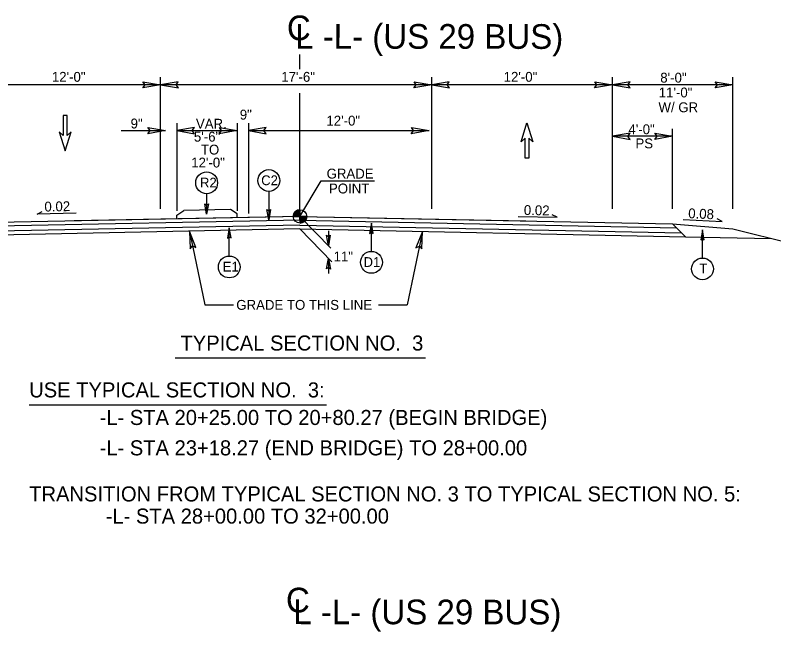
# Model space of a CAD drawing. Extents: x 1901582 to 1902252, y 193723 to 194156.
# Drawn here: x 1902027.7 to 1902078.1, y 194003.9 to 194044.9 of the extents above; entities that cross this region are included whole.
import ezdxf

# ---------------------------------------------------------------- set-up
doc = ezdxf.new("R2010")
doc.units = 0
for name, color, linetype in [('Old_Level_1', 7, 'Continuous'), ('Old_Level_11', 7, 'Continuous'), ('Old_Level_2', 7, 'Continuous'), ('Old_Level_20', 7, 'Continuous'), ('Prop Dimension', 7, 'Continuous'), ('Prop Dimension Text', 7, 'Continuous'), ('Typical Grade Point Symbol CELL', 7, 'Continuous'), ('Typical Pavement Slope Information CELL', 7, 'Continuous'), ('Typical Terminator CELL', 7, 'Continuous'), ('Typical Text Centerline CELL', 7, 'Continuous'), ('Typical Text Grade Point CELL', 7, 'Continuous')]:
    doc.layers.add(name, color=color, linetype=linetype)

# ---------------------------------------------------------------- blocks, each defined once
blk = doc.blocks.new('TERMINATOR')
at = {"layer": 'Typical Terminator CELL'}
blk.add_lwpolyline([(-0.469, 0.081), (0, 0), (-0.471, -0.083), (-0.411, 0)], close=True, dxfattribs=at)

msp = doc.modelspace()

# ---------------------------------------------------------------- linework, layer by layer
at = {"layer": 'Old_Level_1'}
for p, q in [((1902037.376, 194032.05), (1902037.376, 194040.8)), ((1902055.376, 194032.05), (1902055.376, 194040.8)), ((1902067.376, 194032.05), (1902067.376, 194040.8)), ((1902075.376, 194032.047), (1902075.376, 194040.8)), ((1902037.376, 194040.3), (1902025.376, 194040.3)), ((1902055.376, 194040.3), (1902037.376, 194040.3)), ((1902067.376, 194040.3), (1902055.376, 194040.3)), ((1902075.376, 194040.3), (1902067.376, 194040.3)), ((1902038.452, 194037.753), (1902038.452, 194031.927)), ((1902042.452, 194037.753), (1902042.452, 194031.927)), ((1902043.202, 194037.753), (1902043.202, 194031.749)), ((1902071.376, 194032.05), (1902071.376, 194037.381)), ((1902071.376, 194036.881), (1902067.376, 194036.881)), ((1902038.452, 194031.64), (1902038.911, 194031.941)), ((1902042.021, 194032.003), (1902038.911, 194031.941)), ((1902042.452, 194031.72), (1902042.021, 194032.003)), ((1902046.631, 194031.55), (1902009.376, 194030.805)), ((1902046.636, 194031.3), (1902013.376, 194030.635)), ((1902046.631, 194031.55), (1902031.631, 194031.25)), ((1902038.452, 194031.386), (1902038.452, 194031.64)), ((1902042.452, 194031.466), (1902042.452, 194031.72)), ((1902046.631, 194031.55), (1902061.631, 194031.25)), ((1902046.631, 194031.55), (1902071.376, 194031.055)), ((1902046.631, 194031.55), (1902048.68, 194029.434)), ((1902046.631, 194031.3), (1902071.631, 194030.8)), ((1902046.631, 194030.967), (1902013.376, 194030.301)), ((1902046.631, 194030.967), (1902071.971, 194030.46)), ((1902071.376, 194031.055), (1902072.226, 194030.205)), ((1902071.376, 194031.055), (1902075.376, 194030.735)), ((1902046.631, 194030.716), (1902013.376, 194030.051)), ((1902039.293, 194030.57), (1902040.316, 194025.679)), ((1902046.631, 194030.716), (1902072.226, 194030.205)), ((1902046.631, 194030.716), (1902048.738, 194028.541)), ((1902048.522, 194030.596), (1902048.522, 194029.596)), ((1902054.766, 194030.554), (1902053.746, 194025.679)), ((1902075.376, 194030.735), (1902083.376, 194028.735)), ((1902075.376, 194030.735), (1902087.619, 194027.674)), ((1902072.226, 194030.205), (1902077.956, 194030.09)), ((1902048.522, 194028.763), (1902048.522, 194027.763)), ((1902040.316, 194025.679), (1902042.225, 194025.679)), ((1902051.837, 194025.679), (1902053.746, 194025.679))]:
    msp.add_line(p, q, dxfattribs=at)
at = {"layer": 'Old_Level_11'}
for p, q in [((1902046.631, 194041.343), (1902046.631, 194042.3)), ((1902046.631, 194031.55), (1902046.631, 194039.743)), ((1902040.431, 194033.056), (1902040.431, 194031.711)), ((1902044.56, 194033.208), (1902044.56, 194031.334)), ((1902041.935, 194028.917), (1902041.935, 194030.791)), ((1902051.375, 194029.224), (1902051.375, 194031.098)), ((1902073.357, 194028.786), (1902073.357, 194030.66)), ((1902038.339, 194022.144), (1902054.965, 194022.144)), ((1902028.649, 194019.029), (1902048.392, 194019.029))]:
    msp.add_line(p, q, dxfattribs=at)
for points in [[(1902040.546, 194032.383), (1902040.431, 194031.711), (1902040.311, 194032.386), (1902040.431, 194032.301)], [(1902044.675, 194032.005), (1902044.56, 194031.334), (1902044.44, 194032.009), (1902044.56, 194031.923)], [(1902042.051, 194030.12), (1902041.935, 194030.791), (1902041.816, 194030.116), (1902041.935, 194030.202)], [(1902051.49, 194030.426), (1902051.375, 194031.098), (1902051.255, 194030.423), (1902051.375, 194030.508)], [(1902073.473, 194029.988), (1902073.357, 194030.66), (1902073.238, 194029.985), (1902073.357, 194030.07)]]:
    msp.add_lwpolyline(points, close=True, dxfattribs=at)
for centre in [(1902040.431, 194033.782), (1902044.56, 194033.933), (1902041.935, 194028.192), (1902051.375, 194028.499), (1902073.357, 194028.061)]:
    msp.add_circle(centre, 0.725, dxfattribs=at)
at = {"layer": 'Prop Dimension'}
for points in [[(1902031.434, 194037.172), (1902031.163, 194036.922), (1902031.163, 194038.256), (1902030.913, 194038.256), (1902030.913, 194036.922), (1902030.642, 194037.172), (1902031.038, 194035.902)], [(1902031.434, 194037.172), (1902031.163, 194036.922), (1902031.163, 194038.256), (1902030.913, 194038.256), (1902030.913, 194036.922), (1902030.642, 194037.172), (1902031.038, 194035.902)], [(1902062.1, 194036.505), (1902061.829, 194036.755), (1902061.829, 194035.421), (1902061.579, 194035.421), (1902061.579, 194036.755), (1902061.308, 194036.505), (1902061.704, 194037.775)], [(1902062.1, 194036.505), (1902061.829, 194036.755), (1902061.829, 194035.421), (1902061.579, 194035.421), (1902061.579, 194036.755), (1902061.308, 194036.505), (1902061.704, 194037.775)]]:
    msp.add_lwpolyline(points, close=True, dxfattribs=at)
at = {"layer": 'Prop Dimension Text'}
for p, q in [((1902034.756, 194037.253), (1902037.702, 194037.253)), ((1902034.799, 194037.253), (1902037.702, 194037.253)), ((1902038.452, 194037.253), (1902042.452, 194037.253)), ((1902043.202, 194037.253), (1902055.202, 194037.253))]:
    msp.add_line(p, q, dxfattribs=at)
at = {"layer": 'Typical Grade Point Symbol CELL'}
for p, q in [((1902046.631, 194031.55), (1902046.631, 194031.998)), ((1902046.184, 194031.55), (1902046.631, 194031.55)), ((1902046.632, 194031.102), (1902046.631, 194031.55)), ((1902047.079, 194031.55), (1902046.631, 194031.55)), ((1902046.631, 194031.55), (1902046.632, 194031.102))]:
    msp.add_line(p, q, dxfattribs=at)
for points in [[(1902046.251, 194031.786), (1902046.251, 194031.55)], [(1902046.26, 194031.8), (1902046.26, 194031.55)], [(1902046.269, 194031.813), (1902046.269, 194031.55)], [(1902046.278, 194031.824), (1902046.278, 194031.55)], [(1902046.287, 194031.835), (1902046.287, 194031.55)], [(1902046.296, 194031.846), (1902046.296, 194031.55)], [(1902046.305, 194031.856), (1902046.305, 194031.55)], [(1902046.314, 194031.865), (1902046.314, 194031.55)], [(1902046.323, 194031.874), (1902046.323, 194031.55)], [(1902046.332, 194031.882), (1902046.332, 194031.55)], [(1902046.341, 194031.89), (1902046.341, 194031.55)], [(1902046.35, 194031.898), (1902046.35, 194031.55)], [(1902046.359, 194031.905), (1902046.359, 194031.55)], [(1902046.368, 194031.911), (1902046.368, 194031.55)], [(1902046.377, 194031.918), (1902046.377, 194031.55)], [(1902046.386, 194031.924), (1902046.386, 194031.55)], [(1902046.395, 194031.93), (1902046.395, 194031.55)], [(1902046.404, 194031.935), (1902046.404, 194031.55)], [(1902046.412, 194031.94), (1902046.412, 194031.55)], [(1902046.421, 194031.945), (1902046.421, 194031.55)], [(1902046.43, 194031.95), (1902046.43, 194031.55)], [(1902046.439, 194031.954), (1902046.439, 194031.55)], [(1902046.448, 194031.958), (1902046.448, 194031.55)], [(1902046.457, 194031.962), (1902046.457, 194031.55)], [(1902046.466, 194031.966), (1902046.466, 194031.55)], [(1902046.475, 194031.97), (1902046.475, 194031.55)], [(1902046.484, 194031.973), (1902046.484, 194031.55)], [(1902046.493, 194031.976), (1902046.493, 194031.55)], [(1902046.502, 194031.979), (1902046.502, 194031.55)], [(1902046.511, 194031.981), (1902046.511, 194031.55)], [(1902046.52, 194031.984), (1902046.52, 194031.55)], [(1902046.529, 194031.986), (1902046.529, 194031.55)], [(1902046.538, 194031.988), (1902046.538, 194031.55)], [(1902046.547, 194031.99), (1902046.547, 194031.55)], [(1902046.556, 194031.992), (1902046.556, 194031.55)], [(1902046.565, 194031.993), (1902046.565, 194031.55)], [(1902046.574, 194031.994), (1902046.574, 194031.55)], [(1902046.583, 194031.995), (1902046.583, 194031.55)], [(1902046.592, 194031.996), (1902046.592, 194031.55)], [(1902046.6, 194031.997), (1902046.6, 194031.55)], [(1902046.609, 194031.997), (1902046.609, 194031.55)], [(1902046.618, 194031.998), (1902046.618, 194031.55)], [(1902046.627, 194031.998), (1902046.627, 194031.998), (1902046.627, 194031.55)], [(1902046.189, 194031.614), (1902046.189, 194031.55)], [(1902046.198, 194031.659), (1902046.198, 194031.55)], [(1902046.207, 194031.69), (1902046.207, 194031.55)], [(1902046.216, 194031.715), (1902046.216, 194031.55)], [(1902046.224, 194031.736), (1902046.224, 194031.55)], [(1902046.233, 194031.755), (1902046.233, 194031.55)], [(1902046.242, 194031.771), (1902046.242, 194031.55)], [(1902046.638, 194031.55), (1902046.638, 194031.102), (1902046.638, 194031.102)], [(1902046.647, 194031.55), (1902046.647, 194031.102)], [(1902046.656, 194031.55), (1902046.656, 194031.103)], [(1902046.665, 194031.55), (1902046.665, 194031.103)], [(1902046.674, 194031.55), (1902046.674, 194031.104)], [(1902046.683, 194031.55), (1902046.683, 194031.105)], [(1902046.692, 194031.55), (1902046.692, 194031.106)], [(1902046.701, 194031.55), (1902046.701, 194031.108)], [(1902046.71, 194031.55), (1902046.71, 194031.109)], [(1902046.719, 194031.55), (1902046.719, 194031.111)], [(1902046.728, 194031.55), (1902046.728, 194031.113)], [(1902046.737, 194031.55), (1902046.737, 194031.115)], [(1902046.746, 194031.55), (1902046.746, 194031.117)], [(1902046.755, 194031.55), (1902046.755, 194031.12)], [(1902046.764, 194031.55), (1902046.764, 194031.122)], [(1902046.773, 194031.55), (1902046.773, 194031.125)], [(1902046.781, 194031.55), (1902046.781, 194031.128)], [(1902046.79, 194031.55), (1902046.79, 194031.131)], [(1902046.799, 194031.55), (1902046.799, 194031.135)], [(1902046.808, 194031.55), (1902046.808, 194031.139)], [(1902046.817, 194031.55), (1902046.817, 194031.143)], [(1902046.826, 194031.55), (1902046.826, 194031.147)], [(1902046.835, 194031.55), (1902046.835, 194031.151)], [(1902046.844, 194031.55), (1902046.844, 194031.156)], [(1902046.853, 194031.55), (1902046.853, 194031.161)], [(1902046.862, 194031.55), (1902046.862, 194031.166)], [(1902046.871, 194031.55), (1902046.871, 194031.172)], [(1902046.88, 194031.55), (1902046.88, 194031.178)], [(1902046.889, 194031.55), (1902046.889, 194031.184)], [(1902046.898, 194031.55), (1902046.898, 194031.19)], [(1902046.907, 194031.55), (1902046.907, 194031.197)], [(1902046.916, 194031.55), (1902046.916, 194031.204)], [(1902046.925, 194031.55), (1902046.925, 194031.212)], [(1902046.934, 194031.55), (1902046.934, 194031.22)], [(1902046.943, 194031.55), (1902046.943, 194031.228)], [(1902046.952, 194031.55), (1902046.952, 194031.237)], [(1902046.961, 194031.55), (1902046.961, 194031.247)], [(1902046.969, 194031.55), (1902046.969, 194031.257)], [(1902046.978, 194031.55), (1902046.978, 194031.267)], [(1902046.987, 194031.55), (1902046.987, 194031.278)], [(1902046.996, 194031.55), (1902046.996, 194031.29)], [(1902047.005, 194031.55), (1902047.005, 194031.303)], [(1902047.014, 194031.55), (1902047.014, 194031.317)], [(1902047.023, 194031.55), (1902047.023, 194031.333)], [(1902047.032, 194031.55), (1902047.032, 194031.35)], [(1902047.041, 194031.55), (1902047.041, 194031.369)], [(1902047.05, 194031.55), (1902047.05, 194031.39)], [(1902047.059, 194031.55), (1902047.059, 194031.417)], [(1902047.068, 194031.55), (1902047.068, 194031.449)], [(1902047.077, 194031.55), (1902047.077, 194031.501)]]:
    msp.add_lwpolyline(points, dxfattribs=at)
msp.add_circle((1902046.632, 194031.55), 0.448, dxfattribs=at)
for start, end in [(90.0095, 180.0095), (270.0095, 0.0095)]:
    msp.add_arc((1902046.632, 194031.55), 0.448, start, end, dxfattribs=at)
at = {"layer": 'Typical Pavement Slope Information CELL'}
for p, q in [((1902029.174, 194031.709), (1902029.506, 194031.877)), ((1902031.761, 194031.772), (1902029.174, 194031.709)), ((1902061.129, 194031.554), (1902063.716, 194031.5)), ((1902063.716, 194031.5), (1902063.384, 194031.667)), ((1902072.071, 194031.336), (1902074.656, 194031.221)), ((1902074.656, 194031.221), (1902074.327, 194031.396))]:
    msp.add_line(p, q, dxfattribs=at)
at = {"layer": 'Typical Terminator CELL'}
for points in [[(1902036.204, 194040.502), (1902037.376, 194040.3), (1902036.197, 194040.092), (1902036.347, 194040.3)], [(1902038.547, 194040.502), (1902037.376, 194040.3), (1902038.554, 194040.092), (1902038.404, 194040.3)], [(1902054.204, 194040.502), (1902055.376, 194040.3), (1902054.197, 194040.092), (1902054.347, 194040.3)], [(1902056.547, 194040.502), (1902055.376, 194040.3), (1902056.554, 194040.092), (1902056.404, 194040.3)], [(1902066.204, 194040.502), (1902067.376, 194040.3), (1902066.197, 194040.092), (1902066.347, 194040.3)], [(1902068.547, 194040.502), (1902067.376, 194040.3), (1902068.554, 194040.092), (1902068.404, 194040.3)], [(1902074.204, 194040.502), (1902075.376, 194040.3), (1902074.197, 194040.092), (1902074.347, 194040.3)], [(1902036.531, 194037.455), (1902037.702, 194037.253), (1902036.524, 194037.044), (1902036.674, 194037.253)], [(1902039.624, 194037.455), (1902038.452, 194037.253), (1902039.631, 194037.044), (1902039.481, 194037.253)], [(1902041.281, 194037.455), (1902042.452, 194037.253), (1902041.274, 194037.044), (1902041.424, 194037.253)], [(1902044.374, 194037.455), (1902043.202, 194037.253), (1902044.381, 194037.044), (1902044.231, 194037.253)], [(1902054.031, 194037.455), (1902055.202, 194037.253), (1902054.024, 194037.044), (1902054.174, 194037.253)], [(1902068.547, 194037.083), (1902067.376, 194036.881), (1902068.554, 194036.673), (1902068.404, 194036.881)], [(1902070.204, 194037.083), (1902071.376, 194036.881), (1902070.197, 194036.673), (1902070.347, 194036.881)], [(1902039.719, 194029.494), (1902039.293, 194030.57), (1902039.33, 194029.406), (1902039.498, 194029.59)], [(1902054.725, 194029.398), (1902054.766, 194030.554), (1902054.333, 194029.473), (1902054.561, 194029.574)]]:
    msp.add_lwpolyline(points, close=True, dxfattribs=at)
at = {"layer": 'Typical Text Grade Point CELL'}
for p, q in [((1902046.631, 194031.55), (1902048.035, 194033.91)), ((1902048.035, 194033.91), (1902051.573, 194033.91))]:
    msp.add_line(p, q, dxfattribs=at)

# ---------------------------------------------------------------- block references
at = {"layer": 'Old_Level_1', "xscale": 1.5, "yscale": 1.5}
for p, rotation in [((1902048.522, 194029.596), -90), ((1902048.522, 194028.763), 90)]:
    msp.add_blockref('TERMINATOR', p, dxfattribs=dict(at, rotation=rotation))

# ---------------------------------------------------------------- texts
at = {"layer": 'Old_Level_1'}
for s, p in [('12\'-0"', (1902030.155, 194040.498)), ('17\'-6" ', (1902045.389, 194040.498)), ('12\'-0"', (1902060.155, 194040.498)), ('8\'-0"', (1902070.556, 194040.443)), ('11\'-0"', (1902070.453, 194039.459)), ('W/ GR', (1902070.436, 194038.475)), ('9"', (1902042.634, 194037.987)), ('9"', (1902035.384, 194037.398)), ('VAR.', (1902039.721, 194037.382)), ('4\'-0"', (1902068.44, 194037.013)), ('5\'-6" ', (1902039.588, 194036.522)), ('TO ', (1902040.05, 194035.662)), ('12\'-0"', (1902039.407, 194034.802)), ('GRADE TO THIS LINE', (1902042.401, 194025.345))]:
    msp.add_text(s, height=0.656, dxfattribs=at).set_placement(p)
at = {"layer": 'Old_Level_11'}
for s, p in [('TYPICAL SECTION NO.  3', (1902038.695, 194022.638)), ('USE TYPICAL SECTION NO.  3:', (1902028.649, 194019.523)), ('-L- STA 20+25.00 TO 20+80.27 (BEGIN BRIDGE)', (1902033.325, 194017.692)), ('-L- STA 23+18.27 (END BRIDGE) TO 28+00.00', (1902033.325, 194015.673)), ('TRANSITION FROM TYPICAL SECTION NO. 3 TO TYPICAL SECTION NO. 5: ', (1902028.649, 194012.61)), ('-L- STA 28+00.00 TO 32+00.00', (1902033.731, 194011.138))]:
    msp.add_text(s, height=1, dxfattribs=at).set_placement(p)
at = {"layer": 'Old_Level_2'}
for s, rotation, p in [('0.02', 1.1916, (1902029.667, 194031.87)), ('0.02', 358.8084, (1902061.491, 194031.651)), ('0.08', 357.4644, (1902072.399, 194031.438))]:
    msp.add_text(s, height=0.656, rotation=rotation, dxfattribs=at).set_placement(p)
at = {"layer": 'Old_Level_20'}
for s, height, p in [('R2', 0.6491, (1902039.991, 194033.475)), ('C2', 0.6491, (1902044.054, 194033.627)), ('11"', 0.6491, (1902048.869, 194028.568)), ('D1', 0.6491, (1902050.853, 194028.195)), ('E1', 0.6491, (1902041.501, 194027.888)), ('T', 0.649, (1902073.146, 194027.767))]:
    msp.add_text(s, height=height, dxfattribs=at).set_placement(p)
at = {"layer": 'Prop Dimension Text'}
for s, p in [('12\'-0"', (1902048.387, 194037.587)), ('PS', (1902068.906, 194036.075))]:
    msp.add_text(s, height=0.656, dxfattribs=at).set_placement(p)
at = {"layer": 'Typical Text Centerline CELL'}
for height, p in [(1.64, (1902045.763, 194043.26)), (1.641, (1902045.699, 194005.237))]:
    msp.add_text('C', height=height, dxfattribs=at).set_placement(p)
for p in [(1902046.308, 194042.7), (1902046.183, 194004.457)]:
    msp.add_text('L -L- (US 29 BUS)', height=1.64109, rotation=359.9469, dxfattribs=at).set_placement(p)
at = {"layer": 'Typical Text Grade Point CELL'}
for s, p in [('GRADE', (1902048.399, 194034.066)), ('POINT', (1902048.556, 194033.078))]:
    msp.add_text(s, height=0.656, dxfattribs=at).set_placement(p)

doc.saveas('drawing.dxf')
